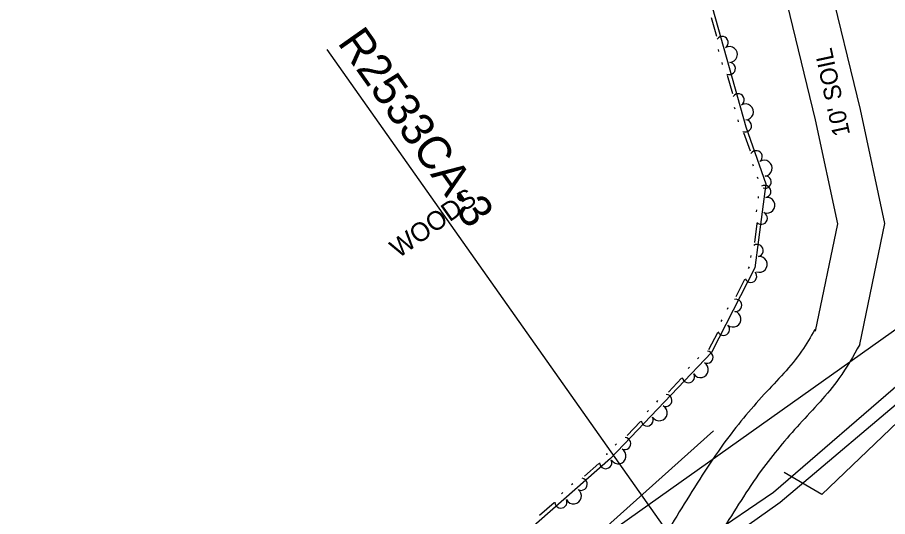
# Model space of a CAD drawing. Extents: x 1577032 to 1581865, y 611492 to 615011.
# Drawn here: x 1578761.3 to 1578946.8, y 612758.2 to 612864.7 of the extents above; entities that cross this region are included whole.
import ezdxf

# ---------------------------------------------------------------- set-up
doc = ezdxf.new("R2010")
doc.units = 0
for name, color, linetype in [('Exist Horizontal Baseline Alignment Station Label', 7, 'Continuous'), ('Exist Right of Way Line', 7, 'Continuous'), ('Exist Utilities Telephone UG FO SUE LOS B', 7, 'Continuous'), ('Exist Utilities Water UG Line SUE LOS B', 7, 'Continuous'), ('Exist Vegetation Woods Line Text', 7, 'Continuous'), ('Old_Level_11', 7, 'Continuous'), ('Old_Level_8', 7, 'Continuous'), ('Scratch_Level_4', 7, 'Continuous')]:
    doc.layers.add(name, color=color, linetype=linetype)

msp = doc.modelspace()

# ---------------------------------------------------------------- linework, layer by layer
at = {"layer": 'Exist Horizontal Baseline Alignment Station Label'}
msp.add_line((1578913.79, 612735.32), (1578827.34, 612857.89), dxfattribs=at)
at = {"layer": 'Exist Right of Way Line'}
msp.add_lwpolyline([(1578124.38, 612213.06), (1579205.66, 612980.92)], dxfattribs=at)
at = {"layer": 'Exist Utilities Telephone UG FO SUE LOS B'}
msp.add_lwpolyline([(1578195.73, 612250.34), (1578241.59, 612286.54), (1578291.86, 612328.33), (1578346.38, 612374.92), (1578396.97, 612410.49), (1578454.86, 612448.05), (1578513.8, 612486.88), (1578570.79, 612520.18), (1578660.13, 612580.57), (1578739.65, 612636.41), (1578799.35, 612673.77), (1578835.75, 612699.17), (1578865.6, 612719.98), (1578923.89, 612761.36), (1578953.65, 612786.53), (1578992.35, 612823.36), (1579016.04, 612847.4), (1579030.15, 612863.93), (1579038.32, 612877.78)], dxfattribs=at)
at = {"layer": 'Exist Utilities Water UG Line SUE LOS B'}
for p, q in [((1578922.48, 612763.46), (1578951.65, 612788.74)), ((1578863.65, 612723.62), (1578922.48, 612763.46))]:
    msp.add_line(p, q, dxfattribs=at)
at = {"layer": 'Old_Level_11'}
for points in [[(1578936.43, 613061.4), (1578936.82, 613051.9), (1578932.5, 613025.42), (1578927.62, 613010.17), (1578914.45, 613005.86), (1578905.3, 612990.25), (1578892.31, 612973.37), (1578878.2, 612962.82), (1578865.77, 612948.47), (1578869.23, 612935.25), (1578877.16, 612918.88), (1578885.44, 612906.76), (1578897.93, 612889.28), (1578909.46, 612866.72), (1578916.54, 612841.37), (1578920.8, 612829.24)], [(1578909.18, 612864.68), (1578910.28, 612860.73)], [(1578910.66, 612857.85), (1578910.77, 612857.46)], [(1578911.43, 612855.09), (1578911.54, 612854.69)], [(1578912.6, 612852.44), (1578913.7, 612848.49)], [(1578914.08, 612845.61), (1578914.19, 612845.21)], [(1578914.85, 612842.85), (1578914.96, 612842.45)], [(1578916.1, 612840.16), (1578917.46, 612836.29)], [(1578918.02, 612833.44), (1578918.16, 612833.06)], [(1578918.97, 612830.74), (1578919.11, 612830.35)], [(1578920.8, 612829.24), (1578918.52, 612811.31), (1578909.27, 612793.26), (1578887.7, 612770.64), (1578854.39, 612741.35)], [(1578919.22, 612826.54), (1578919.17, 612826.14)], [(1578918.86, 612823.7), (1578918.8, 612823.29)], [(1578918.9, 612820.8), (1578918.38, 612816.73)], [(1578917.61, 612813.93), (1578917.56, 612813.53)], [(1578917.25, 612811.53), (1578917.06, 612811.17)], [(1578916.3, 612808.79), (1578914.43, 612805.14)], [(1578912.76, 612802.77), (1578912.57, 612802.4)], [(1578911.45, 612800.21), (1578911.27, 612799.85)], [(1578910.51, 612797.47), (1578908.64, 612793.82)], [(1578906.55, 612792.19), (1578906.27, 612791.89)], [(1578904.57, 612790.11), (1578904.28, 612789.81)], [(1578902.88, 612787.75), (1578900.05, 612784.78)], [(1578897.77, 612782.99), (1578897.49, 612782.69)], [(1578895.79, 612780.91), (1578895.51, 612780.61)], [(1578894.11, 612778.55), (1578891.28, 612775.58)], [(1578889, 612773.79), (1578888.72, 612773.49)], [(1578887.02, 612771.71), (1578886.85, 612771.53), (1578886.81, 612771.5)], [(1578885.23, 612769.56), (1578882.15, 612766.85)], [(1578879.72, 612765.27), (1578879.41, 612764.99)], [(1578877.56, 612763.37), (1578877.26, 612763.1)], [(1578875.68, 612761.17), (1578872.6, 612758.46)]]:
    msp.add_lwpolyline(points, dxfattribs=at)
for centre, radius, start, end in [((1578911.51, 612859.37), 1.3, 304.0448, 144.8414), ((1578913.08, 612856.83), 1.69, 271.5736, 119.6461), ((1578913.06, 612853.84), 1.3, 246.3783, 87.1749), ((1578914.93, 612847.13), 1.3, 304.0448, 144.8414), ((1578916.5, 612844.58), 1.69, 271.5736, 119.6461), ((1578916.48, 612841.6), 1.3, 246.3783, 87.1749), ((1578918.77, 612835.01), 1.3, 307.7773, 148.5738), ((1578920.5, 612832.58), 1.69, 275.3061, 123.3786), ((1578920.68, 612829.6), 1.3, 250.1108, 90.9074), ((1578920.59, 612827.61), 1.3, 281.1716, 121.9681), ((1578921.05, 612824.66), 1.69, 248.7004, 96.7729), ((1578919.87, 612821.91), 1.3, 223.5051, 64.3017), ((1578918.99, 612815), 1.3, 281.1716, 121.9681), ((1578919.44, 612812.05), 1.69, 248.7004, 96.7729), ((1578917.6, 612809.51), 1.3, 203.6459, 44.4425), ((1578914.42, 612803.3), 1.3, 261.3124, 102.109), ((1578913.84, 612800.38), 1.69, 228.8412, 76.9137), ((1578911.8, 612798.19), 1.3, 203.6459, 44.4425), ((1578908.29, 612792.23), 1.3, 244.7844, 85.5809), ((1578906.9, 612789.58), 1.69, 212.3132, 60.3857), ((1578904.32, 612788.07), 1.3, 187.1179, 27.9145), ((1578899.51, 612783.03), 1.3, 244.7844, 85.5809), ((1578898.12, 612780.38), 1.69, 212.3132, 60.3857), ((1578895.55, 612778.87), 1.3, 187.1179, 27.9145), ((1578890.74, 612773.83), 1.3, 244.7844, 85.5809), ((1578889.35, 612771.19), 1.69, 212.3132, 60.3857), ((1578886.69, 612769.76), 1.3, 182.1002, 22.8968), ((1578881.46, 612765.15), 1.3, 239.7667, 80.5633), ((1578879.84, 612762.64), 1.69, 207.2955, 55.368), ((1578877.15, 612761.36), 1.3, 182.1002, 22.8968)]:
    msp.add_arc(centre, radius, start, end, dxfattribs=at)
at = {"layer": 'Old_Level_8'}
for points in [[(1578949, 612778.47), (1578932.79, 612762.95), (1578924.76, 612767.67)], [(1578811.26, 612691.49), (1578840.64, 612714.59), (1578909.67, 612776.54)]]:
    msp.add_lwpolyline(points, dxfattribs=at)
at = {"layer": 'Scratch_Level_4'}
for points in [[(1578940.86, 612794.97), (1578946.23, 612820.74), (1578941.01, 612845.06), (1578934.13, 612873.43), (1578923.99, 612895.62), (1578912.58, 612913.9)], [(1578931.4, 612797.81), (1578936.17, 612820.71), (1578931.41, 612842.86), (1578924.78, 612870.19), (1578915.3, 612890.95), (1578904.23, 612908.68)]]:
    msp.add_lwpolyline(points, dxfattribs=at)
for points in [[(1578931.27, 612798.14), (1578928.45, 612793.52), (1578920.51, 612784.35), (1578911.91, 612773.89), (1578902.91, 612760.1), (1578895.54, 612745.6), (1578894.5, 612733.91), (1578898.97, 612724.22)], [(1578940.86, 612794.97), (1578936.42, 612787.7), (1578928.03, 612778), (1578919.86, 612768.06), (1578911.45, 612755.16), (1578905.18, 612742.84), (1578904.54, 612735.65), (1578907.16, 612729.96)]]:
    msp.add_spline(points, degree=3, dxfattribs=at)

# ---------------------------------------------------------------- texts
at = {"layer": 'Exist Horizontal Baseline Alignment Station Label'}
msp.add_text('R2533CA-3', height=7, rotation=305.1961, dxfattribs=at).set_placement((1578829.38, 612859.33))
at = {"layer": 'Exist Vegetation Woods Line Text'}
msp.add_text('WOODS', height=4, rotation=35.38, dxfattribs=at).set_placement((1578842.53, 612813.26))
at = {"layer": 'Scratch_Level_4'}
msp.add_text("10' SOIL", height=3.691, rotation=102.1201, dxfattribs=at).set_placement((1578938.82, 612839.81))

doc.saveas('drawing.dxf')
